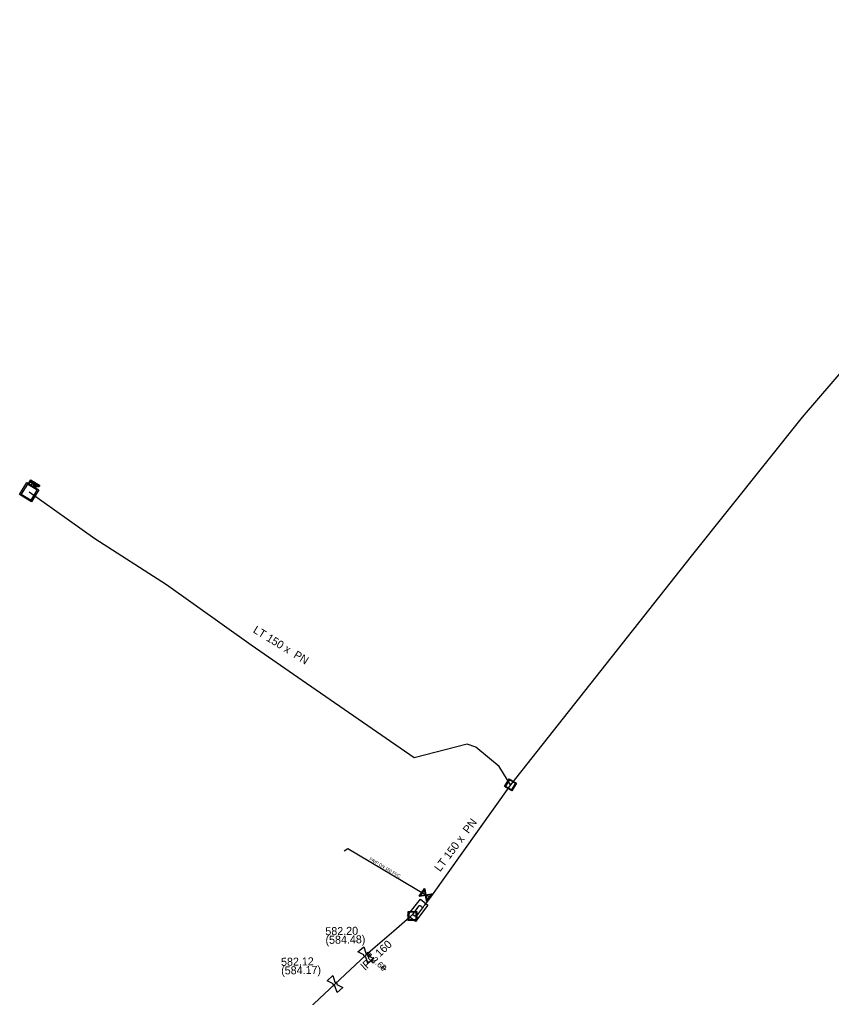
# Model space of a CAD drawing. Extents: x -643544 to -637295, y -1119190 to -1111715.
# Drawn here: x -641919 to -641787.1, y -1116219.3 to -1116060.4 of the extents above; entities that cross this region are included whole.
import ezdxf

# ---------------------------------------------------------------- set-up
doc = ezdxf.new("R2010")
doc.units = 0
for name, color, linetype in [('Default', 7, 'Continuous'), ('VP Kótování', 7, 'Continuous'), ('VP Lomový bod', 7, 'Continuous'), ('VP Lomový bod - popis', 7, 'Continuous'), ('VP Podzemní objekt - půdorys', 7, 'Continuous'), ('VP Popis přípojky', 7, 'Continuous'), ('VP Přípojka', 7, 'Continuous'), ('VP Řad', 7, 'Continuous'), ('VP Řad - popis', 7, 'Continuous'), ('VP Šachta', 7, 'Continuous'), ('VP Šoupě', 7, 'Continuous')]:
    doc.layers.add(name, color=color, linetype=linetype)

msp = doc.modelspace()

# ---------------------------------------------------------------- linework, layer by layer
at = {"layer": 'Default'}
for points in [[(-641917, -1116135.35), (-641916.95, -1116135.38), (-641916.92, -1116135.41), (-641916.89, -1116135.43), (-641916.88, -1116135.47), (-641916.86, -1116135.5), (-641916.87, -1116135.54), (-641916.87, -1116135.57), (-641916.89, -1116135.61), (-641916.93, -1116135.67), (-641917, -1116135.69), (-641917.06, -1116135.71), (-641917.17, -1116135.65)], [(-641917.13, -1116135.59), (-641917.07, -1116135.63), (-641917.03, -1116135.62), (-641916.99, -1116135.62), (-641916.96, -1116135.57), (-641916.94, -1116135.54), (-641916.95, -1116135.51), (-641916.95, -1116135.48), (-641916.97, -1116135.46), (-641916.98, -1116135.44), (-641917.03, -1116135.42)], [(-641916.69, -1116136.07), (-641916.7, -1116136.01), (-641916.7, -1116135.97), (-641916.7, -1116135.94), (-641916.71, -1116135.92), (-641916.72, -1116135.9), (-641916.74, -1116135.89), (-641916.74, -1116135.88), (-641916.77, -1116135.87)], [(-641916.67, -1116135.85), (-641916.63, -1116135.88), (-641916.6, -1116135.88), (-641916.57, -1116135.89), (-641916.54, -1116135.88), (-641916.52, -1116135.86), (-641916.5, -1116135.84), (-641916.48, -1116135.81), (-641916.49, -1116135.77), (-641916.5, -1116135.73), (-641916.56, -1116135.7)], [(-641916.53, -1116135.64), (-641916.46, -1116135.68), (-641916.44, -1116135.71), (-641916.41, -1116135.75), (-641916.41, -1116135.79), (-641916.41, -1116135.84), (-641916.43, -1116135.88), (-641916.47, -1116135.93), (-641916.52, -1116135.95), (-641916.58, -1116135.96), (-641916.65, -1116135.93), (-641916.64, -1116135.96), (-641916.63, -1116135.98), (-641916.62, -1116136.02), (-641916.62, -1116136.08)], [(-641915.9, -1116136.02), (-641915.85, -1116136.05), (-641915.83, -1116136.07), (-641915.8, -1116136.1), (-641915.78, -1116136.13), (-641915.77, -1116136.17), (-641915.77, -1116136.2), (-641915.78, -1116136.24), (-641915.8, -1116136.28), (-641915.84, -1116136.34), (-641915.9, -1116136.36), (-641915.97, -1116136.38), (-641916.07, -1116136.32)], [(-641916.04, -1116136.26), (-641915.97, -1116136.3), (-641915.93, -1116136.29), (-641915.89, -1116136.28), (-641915.87, -1116136.24), (-641915.85, -1116136.21), (-641915.85, -1116136.18), (-641915.85, -1116136.15), (-641915.87, -1116136.13), (-641915.89, -1116136.11), (-641915.93, -1116136.08)], [(-641862.76, -1116212.77), (-641862.81, -1116212.77), (-641862.86, -1116212.76), (-641862.94, -1116212.73), (-641863, -1116212.66), (-641863.05, -1116212.6), (-641863.07, -1116212.52), (-641863.08, -1116212.47), (-641863.07, -1116212.41)], [(-641862.76, -1116212.15), (-641862.71, -1116212.15), (-641862.66, -1116212.17), (-641862.58, -1116212.19), (-641862.52, -1116212.26), (-641862.47, -1116212.32), (-641862.45, -1116212.4), (-641862.44, -1116212.46), (-641862.45, -1116212.51)], [(-641867.77, -1116217.47), (-641867.82, -1116217.47), (-641867.87, -1116217.46), (-641867.95, -1116217.43), (-641868.01, -1116217.36), (-641868.06, -1116217.3), (-641868.08, -1116217.22), (-641868.09, -1116217.17), (-641868.08, -1116217.11)], [(-641867.77, -1116216.85), (-641867.72, -1116216.85), (-641867.67, -1116216.87), (-641867.59, -1116216.89), (-641867.53, -1116216.96), (-641867.48, -1116217.02), (-641867.46, -1116217.1), (-641867.45, -1116217.16), (-641867.46, -1116217.21)]]:
    msp.add_open_spline(points, degree=3, dxfattribs=at)
at = {"layer": 'VP Kótování'}
for points in [[(-641862.52, -1116211.98), (-641861.98, -1116212.51)], [(-641859.58, -1116214.84), (-641860.12, -1116214.31)]]:
    msp.add_lwpolyline(points, dxfattribs=at)
at = {"layer": 'VP Lomový bod'}
for points in [[(-641863.07, -1116212.41), (-641864.05, -1116211.92), (-641863.1, -1116211.1), (-641862.76, -1116212.15)], [(-641862.45, -1116212.51), (-641861.47, -1116213)], [(-641861.47, -1116213), (-641862.42, -1116213.82), (-641862.76, -1116212.77)], [(-641868.08, -1116217.11), (-641869.06, -1116216.62), (-641868.11, -1116215.8), (-641867.77, -1116216.85)], [(-641867.46, -1116217.21), (-641866.48, -1116217.7)], [(-641866.48, -1116217.7), (-641867.43, -1116218.52), (-641867.77, -1116217.47)]]:
    msp.add_lwpolyline(points, dxfattribs=at)
at = {"layer": 'VP Podzemní objekt - půdorys'}
msp.add_lwpolyline([(-641856.01, -1116206.01), (-641853.9, -1116203.36), (-641852.66, -1116204.33), (-641854.68, -1116207.01)], close=True, dxfattribs=at)
at = {"layer": 'VP Přípojka'}
msp.add_lwpolyline([(-641852.27, -1116203.07), (-641853.03, -1116202.71), (-641865.7, -1116195.2), (-641866.26, -1116195.57)], dxfattribs=at)
at = {"layer": 'VP Řad'}
for points in [[(-641738.32, -1116060.45), (-641763.62, -1116092.18), (-641791.9, -1116125.08), (-641809.9, -1116147.66), (-641839.25, -1116184.78)], [(-641839.25, -1116184.78), (-641841.1, -1116181.82), (-641844.89, -1116178.65), (-641846.29, -1116178.16), (-641854.88, -1116180.38), (-641873.09, -1116167.83), (-641881.39, -1116162.08), (-641895.11, -1116152.3), (-641906.76, -1116144.85), (-641917.43, -1116137.24)], [(-641839.25, -1116184.78), (-641852.27, -1116203.07), (-641853.26, -1116204.38)], [(-641853.54, -1116204.76), (-641853.79, -1116204.56), (-641853.91, -1116204.47), (-641854.07, -1116204.43), (-641854.19, -1116204.51), (-641855.2, -1116205.85), (-641855.3, -1116205.98), (-641855.39, -1116206.1), (-641855.49, -1116206.21), (-641855.6, -1116206.32), (-641858.2, -1116208.55), (-641862.76, -1116212.46), (-641867.77, -1116217.16), (-641876.27, -1116225.16)], [(-641853.26, -1116204.38), (-641853.35, -1116204.5), (-641853.44, -1116204.62), (-641853.54, -1116204.76), (-641854.54, -1116206.09), (-641854.66, -1116206.16), (-641854.82, -1116206.13), (-641855.06, -1116205.95), (-641855.2, -1116205.85)]]:
    msp.add_lwpolyline(points, dxfattribs=at)
at = {"layer": 'VP Šachta'}
for points in [[(-641915.86, -1116136.84), (-641917.07, -1116138.82), (-641919, -1116137.64), (-641917.8, -1116135.66), (-641915.86, -1116136.84)], [(-641917.73, -1116135.93), (-641918.73, -1116137.58), (-641917.13, -1116138.55), (-641916.13, -1116136.9), (-641917.73, -1116135.93)], [(-641917.48, -1116135.73), (-641917.18, -1116135.24), (-641917, -1116135.35)], [(-641917.17, -1116135.65), (-641917.29, -1116135.57), (-641917.42, -1116135.77), (-641917.48, -1116135.73)], [(-641917.03, -1116135.42), (-641917.15, -1116135.34), (-641917.26, -1116135.52)], [(-641917.26, -1116135.52), (-641917.13, -1116135.59)], [(-641917.04, -1116136), (-641916.74, -1116135.51), (-641916.53, -1116135.64)], [(-641916.77, -1116135.87), (-641916.84, -1116135.82), (-641916.98, -1116136.04), (-641917.04, -1116136)], [(-641916.56, -1116135.7), (-641916.71, -1116135.6), (-641916.81, -1116135.77)], [(-641916.81, -1116135.77), (-641916.67, -1116135.85)], [(-641916.62, -1116136.08), (-641916.61, -1116136.26), (-641916.69, -1116136.21), (-641916.69, -1116136.07)], [(-641916.55, -1116136.3), (-641916.25, -1116135.81), (-641916.18, -1116135.85), (-641916.48, -1116136.34), (-641916.55, -1116136.3)], [(-641916.38, -1116136.4), (-641916.09, -1116135.91), (-641915.9, -1116136.02)], [(-641916.07, -1116136.32), (-641916.2, -1116136.24), (-641916.32, -1116136.44), (-641916.38, -1116136.4)], [(-641915.93, -1116136.08), (-641916.06, -1116136.01), (-641916.16, -1116136.18)], [(-641916.16, -1116136.18), (-641916.04, -1116136.26)], [(-641838.27, -1116184.53), (-641839.03, -1116185.77), (-641840.23, -1116185.04), (-641839.48, -1116183.8), (-641838.27, -1116184.53)], [(-641839.44, -1116183.96), (-641840.07, -1116184.99), (-641839.06, -1116185.6), (-641838.44, -1116184.57), (-641839.44, -1116183.96)], [(-641854.45, -1116205.37), (-641854.45, -1116206.82), (-641855.87, -1116206.82), (-641855.87, -1116205.37), (-641854.45, -1116205.37)], [(-641855.75, -1116205.49), (-641855.75, -1116206.7), (-641854.57, -1116206.7), (-641854.57, -1116205.49), (-641855.75, -1116205.49)]]:
    msp.add_lwpolyline(points, dxfattribs=at)
at = {"layer": 'VP Šoupě'}
for points in [[(-641851.99, -1116202.52), (-641852.85, -1116203.75), (-641852.9, -1116203.71), (-641852.92, -1116203.59), (-641853.07, -1116202.76), (-641854.02, -1116202.93), (-641854.08, -1116202.89), (-641853.22, -1116201.66), (-641853.16, -1116201.7), (-641853, -1116202.66), (-641852.17, -1116202.51), (-641852.04, -1116202.48), (-641851.99, -1116202.52)], [(-641853.91, -1116202.82), (-641853.08, -1116202.67), (-641853.23, -1116201.84), (-641853.91, -1116202.82)], [(-641852.16, -1116202.6), (-641852.98, -1116202.74), (-641852.84, -1116203.57), (-641852.16, -1116202.6)]]:
    msp.add_lwpolyline(points, dxfattribs=at)

# ---------------------------------------------------------------- texts
at = {"layer": 'VP Kótování'}
for s, rotation, p in [('z', 315.8886, (-641862.69, -1116212.52)), ('2.60', 315.8886, (-641861.84, -1116213.34)), ('z', 135.8886, (-641859.41, -1116214.3))]:
    msp.add_text(s, height=1, rotation=rotation, dxfattribs=at).set_placement(p)
at = {"layer": 'VP Lomový bod - popis'}
for s, p in [('582.20', (-641869.32, -1116209.24)), ('(584.48)', (-641869.3, -1116210.64)), ('582.12', (-641876.52, -1116214.21)), ('(584.17)', (-641876.5, -1116215.61))]:
    msp.add_text(s, height=1.3, rotation=1, dxfattribs=at).set_placement(p)
at = {"layer": 'VP Popis přípojky'}
msp.add_text('PRIP DN 160 PVC', height=0.5, rotation=329.3719, dxfattribs=at).set_placement((-641862.25, -1116196.98))
at = {"layer": 'VP Řad - popis'}
for s, rotation, p in [('LT 150 x  PN ', 328.3143, (-641881.19, -1116159.96)), ('LT 150 x  PN ', 53.255, (-641850.7, -1116199.01)), ('lPE 160', 43.1714, (-641862.83, -1116215.03))]:
    msp.add_text(s, height=1.3, rotation=rotation, dxfattribs=at).set_placement(p)

doc.saveas('drawing.dxf')
